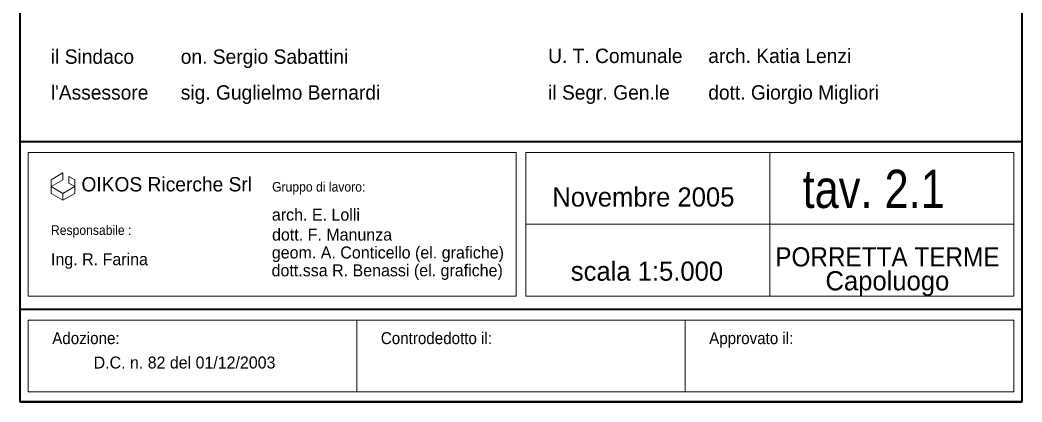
# Model space of a CAD drawing. Extents: x 654952 to 658955, y 890426 to 894481.
# Drawn here: x 654952 to 656002, y 892994 to 893394 of the extents above; entities that cross this region are included whole.
import ezdxf
from ezdxf.enums import TextEntityAlignment as Align

# ---------------------------------------------------------------- set-up
doc = ezdxf.new("R2010")
doc.units = 0
doc.header["$LTSCALE"] = 4
doc.layers.add('60', color=7, linetype='Continuous', lineweight=35)

msp = doc.modelspace()

# ---------------------------------------------------------------- linework, layer by layer
at = {"layer": '60', "lineweight": 40}
for p, q in [((654952.15, 893267.27), (656002.15, 893267.27)), ((654952.15, 893091.77), (656002.15, 893091.77)), ((654952.15, 892994.49), (656002.15, 892994.49))]:
    msp.add_line(p, q, dxfattribs=at)
at = {"layer": '60', "lineweight": 13}
for p, q in [((654960.68, 893255.73), (654960.68, 893105.3)), ((654960.68, 893255.73), (655472.13, 893255.73)), ((655472.13, 893255.73), (655472.13, 893105.3)), ((655482.16, 893255.73), (655482.16, 893105.3)), ((655482.16, 893255.73), (655993.63, 893255.73)), ((655737.91, 893255.73), (655737.91, 893105.3)), ((655993.63, 893255.73), (655993.63, 893105.3)), ((655482.14, 893180.52), (655993.61, 893180.52)), ((654960.68, 893105.3), (655472.13, 893105.3)), ((655482.16, 893105.3), (655993.63, 893105.3)), ((654960.68, 893080.24), (655993.63, 893080.24)), ((654960.68, 893080.23), (654960.68, 893005.03)), ((655304.98, 893080.23), (655304.98, 893005.03)), ((655649.31, 893080.23), (655649.31, 893005.03)), ((655993.63, 893080.23), (655993.63, 893005.03)), ((654960.68, 893005.03), (655993.63, 893005.03))]:
    msp.add_line(p, q, dxfattribs=at)
at = {"layer": '60', "lineweight": 40}
msp.add_lwpolyline([(656002.16, 894480.73), (656002.16, 892994.48), (654952.16, 892994.48), (654952.16, 894480.73)], close=True, dxfattribs=at)
at = {"layer": '60', "lineweight": 13}
for points in [[(654997.06, 893234.18), (654984.65, 893227.04), (654984.65, 893219.88), (654997.06, 893227.04)], [(655009.47, 893227.04), (655003.26, 893230.61), (655003.26, 893223.46), (655009.47, 893219.88)], [(654997.06, 893212.71), (654984.65, 893219.88), (654984.65, 893212.71), (654997.06, 893205.57)], [(655009.47, 893219.88), (654997.06, 893212.71), (654997.06, 893205.57), (655009.47, 893212.71)]]:
    msp.add_lwpolyline(points, close=True, dxfattribs=at)

# ---------------------------------------------------------------- texts
at = {"layer": '60'}
for s, height, p in [('il Sindaco', 15.04, (654984.44, 893348.48)), ('on. Sergio Sabattini', 15.04, (655120.58, 893348.48)), ('U. T. Comunale', 15.04, (655505.62, 893349.28)), ('arch. Katia Lenzi', 15.04, (655673.41, 893349.28)), ("l'Assessore", 15.04, (654984.47, 893310.96)), ('sig. Guglielmo Bernardi', 15.04, (655120.61, 893310.96)), ('il Segr. Gen.le', 15.04, (655505.62, 893310.96)), ('dott. Giorgio Migliori', 15.04, (655673.41, 893310.96)), ('OIKOS Ricerche Srl', 15.04, (655016.49, 893214.86)), ('arch. E. Lolli', 12.54, (655216.07, 893184.26)), ('dott. F. Manunza', 12.54, (655216.24, 893163.38)), ('Ing. R. Farina', 12.54, (654984.59, 893137.63)), ('geom. A. Conticello (el. grafiche)', 12.54, (655216.02, 893144.68)), ('dott.ssa R. Benassi (el. grafiche)', 12.54, (655215.79, 893125.98)), ('scala 1:5.000     ', 20.06, (655529.39, 893121.41)), ('D.C. n. 82 del 01/12/2003', 12.5, (655029.29, 893029.49))]:
    msp.add_text(s, height=height, dxfattribs=at).set_placement(p)
for s, height, width, p in [('tav. 2.1', 40, 0.85, (655772.24, 893197.53)), ('Gruppo di lavoro:', 10.03, 0.95, (655216.29, 893214.68)), ('Responsabile :', 10.03, 0.95, (654984.57, 893169.33)), ('Adozione:', 12.5, 0.95, (654985.89, 893055.03)), ('Controdedotto il:', 12.5, 0.95, (655330.27, 893055.03)), ('Approvato il:', 12.5, 0.95, (655674.34, 893055.03))]:
    msp.add_text(s, height=height, dxfattribs=dict(at, width=width)).set_placement(p)
for s, p in [('Novembre 2005', (655605.39, 893199.03)), ('Capoluogo', (655861.11, 893111.3))]:
    msp.add_text(s, height=20.06, dxfattribs=at).set_placement(p, align=Align.CENTER)
at = {"layer": '60', "width": 0.95}
msp.add_text('PORRETTA TERME', height=20.06, dxfattribs=at).set_placement((655861.12, 893136.35), align=Align.CENTER)

doc.saveas('drawing.dxf')
